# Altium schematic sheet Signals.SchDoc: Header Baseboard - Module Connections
size A4; Organization: Trenz Electronic GmbH; DocumentNumber: TE0304 - Demo Baseboard; Revision: 00; SheetNumber: 2; SheetTotal: 4; Date: 2009-04-16
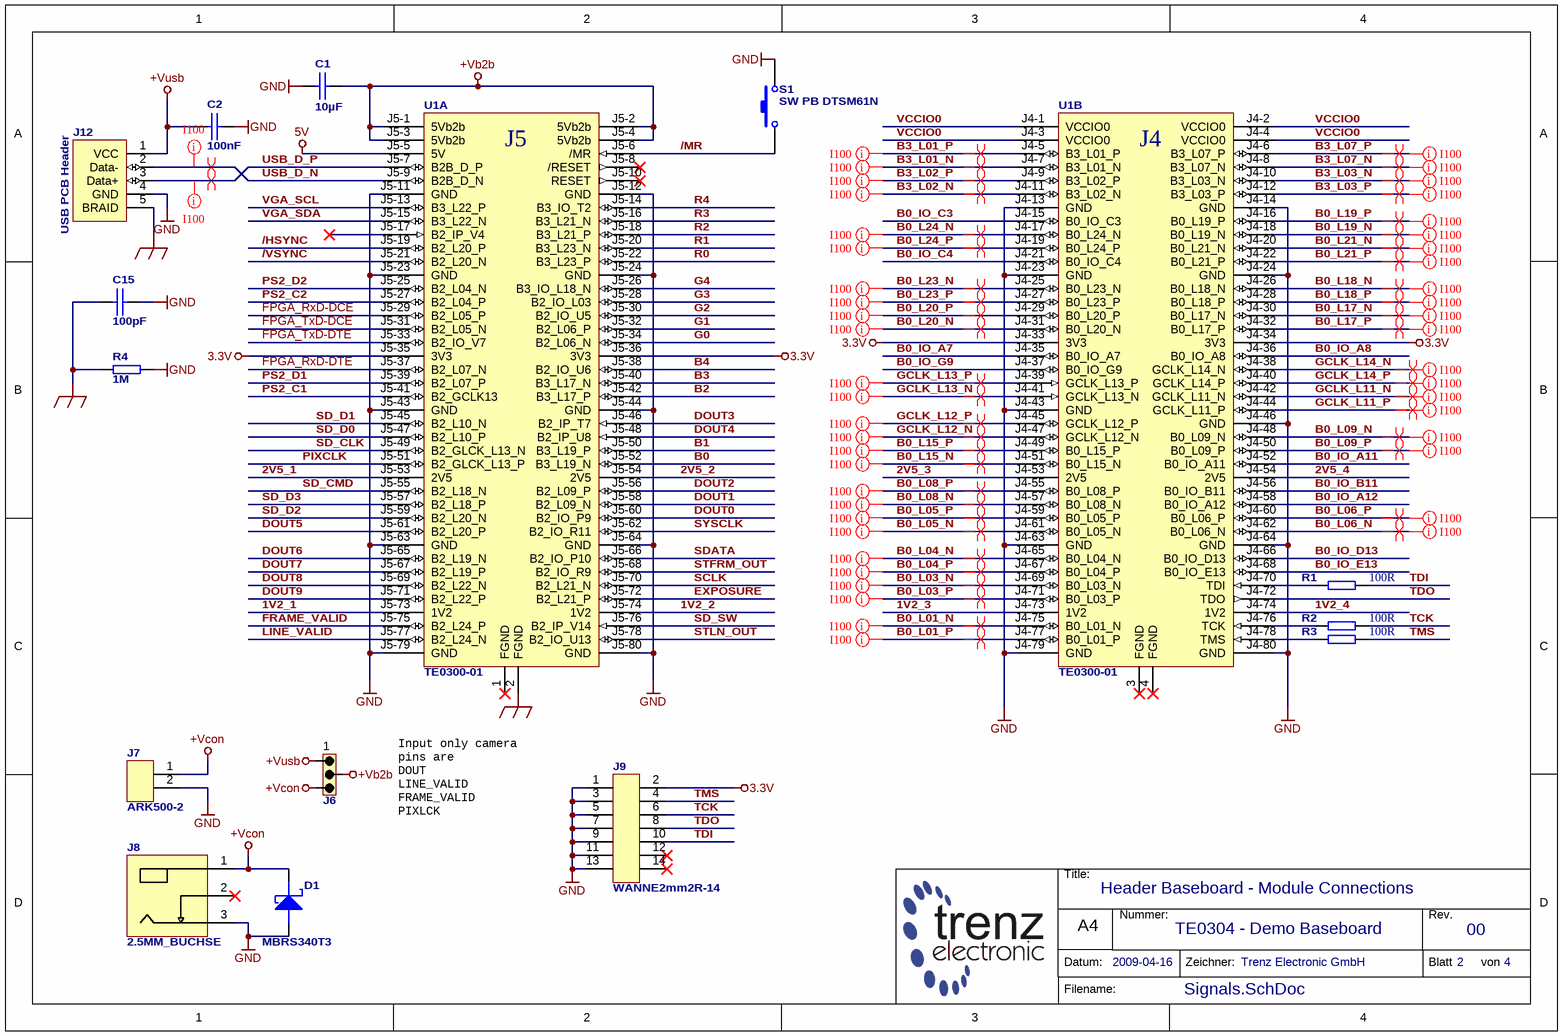
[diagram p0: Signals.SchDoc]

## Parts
C1  10µF  [CAPC2012N]
C2  100nF  [CAPC1608N]
C15  100pF  [CAPC3216N]
D1  MBRS340T3  [MBRS340T3]
J6  JUMPER2.54-3  [JUMPER2_54-3]  (value not drawn)
J7  ARK500-2  [ARK500-2]
J8  2.5MM_BUCHSE  [WS-DC001]
J9  WANNE2mm2R-14  [WANNE2mm2R-14]
J12  USB PCB Header  [14191]
R1  100R  [RESC1609N]
R2  100R  [RESC1609N]
R3  100R  [RESC1609N]
R4  1M  [RESC3216N]
S1  SW PB DTSM61N  [DTSM61N]
U1  TE0300-01  [TE0300-01]  (parts A,B of 2)

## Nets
3.3V: J9.2 U1.J4-33(3V3) U1.J4-34(3V3) U1.J5-35(3V3) U1.J5-36(3V3)
5V: U1.J5-5(5V)
+Vb2b: C1.2 J6.2 U1.J5-1(5Vb2b) U1.J5-2(5Vb2b) U1.J5-3(5Vb2b) U1.J5-4(5Vb2b)
+Vcon: D1.1(CATHODE) J6.3 J7.1 J8.1
+Vusb: C2.1 J6.1 J12.1(VCC)
FGND: C15.1 J12.5(BRAID) R4.1 U1.2(FGND)
GND: C1.1 C2.2 C15.2 D1.2(ANODE) J7.2 J8.3 J9.1 J9.3 J9.5 J9.7 J9.9 J9.11 J9.13 J12.4(GND) R4.2 S1.2 U1.J4-13(GND) U1.J4-14(GND) U1.J4-23(GND) U1.J4-24(GND) U1.J4-43(GND) U1.J4-46(GND) U1.J4-63(GND) U1.J4-64(GND) U1.J4-79(GND) U1.J4-80(GND) U1.J5-11(GND) U1.J5-12(GND) U1.J5-23(GND) U1.J5-24(GND) U1.J5-43(GND) U1.J5-44(GND) U1.J5-63(GND) U1.J5-64(GND) U1.J5-79(GND) U1.J5-80(GND)
1V2_1: U1.J5-73(1V2)
1V2_2: U1.J5-74(1V2)
1V2_3: U1.J4-73(1V2)
1V2_4: U1.J4-74(1V2)
2V5_1: U1.J5-53(2V5)
2V5_2: U1.J5-54(2V5)
2V5_3: U1.J4-53(2V5)
2V5_4: U1.J4-54(2V5)
/HSYNC: U1.J5-19(B2_L20_P)
/MR: S1.1 U1.J5-6(/MR)
/VSYNC: U1.J5-21(B2_L20_N)
B0: U1.J5-52(B3_L19_N)
B0_IO_A7: U1.J4-35(B0_IO_A7)
B0_IO_A8: U1.J4-36(B0_IO_A8)
B0_IO_A11: U1.J4-52(B0_IO_A11)
B0_IO_A12: U1.J4-58(B0_IO_A12)
B0_IO_B11: U1.J4-56(B0_IO_B11)
B0_IO_C3: U1.J4-15(B0_IO_C3)
B0_IO_C4: U1.J4-21(B0_IO_C4)
B0_IO_D13: U1.J4-66(B0_IO_D13)
B0_IO_E13: U1.J4-68(B0_IO_E13)
B0_IO_G9: U1.J4-37(B0_IO_G9)
B0_L01_N: U1.J4-75(B0_L01_N)
B0_L01_P: U1.J4-77(B0_L01_P)
B0_L03_N: U1.J4-69(B0_L03_N)
B0_L03_P: U1.J4-71(B0_L03_P)
B0_L04_N: U1.J4-65(B0_L04_N)
B0_L04_P: U1.J4-67(B0_L04_P)
B0_L05_N: U1.J4-61(B0_L05_N)
B0_L05_P: U1.J4-59(B0_L05_P)
B0_L06_N: U1.J4-62(B0_L06_N)
B0_L06_P: U1.J4-60(B0_L06_P)
B0_L08_N: U1.J4-57(B0_L08_N)
B0_L08_P: U1.J4-55(B0_L08_P)
B0_L09_N: U1.J4-48(B0_L09_N)
B0_L09_P: U1.J4-50(B0_L09_P)
B0_L15_N: U1.J4-51(B0_L15_N)
B0_L15_P: U1.J4-49(B0_L15_P)
B0_L17_N: U1.J4-30(B0_L17_N)
B0_L17_P: U1.J4-32(B0_L17_P)
B0_L18_N: U1.J4-26(B0_L18_N)
B0_L18_P: U1.J4-28(B0_L18_P)
B0_L19_N: U1.J4-18(B0_L19_N)
B0_L19_P: U1.J4-16(B0_L19_P)
B0_L20_N: U1.J4-31(B0_L20_N)
B0_L20_P: U1.J4-29(B0_L20_P)
B0_L21_N: U1.J4-20(B0_L21_N)
B0_L21_P: U1.J4-22(B0_L21_P)
B0_L23_N: U1.J4-25(B0_L23_N)
B0_L23_P: U1.J4-27(B0_L23_P)
B0_L24_N: U1.J4-17(B0_L24_N)
B0_L24_P: U1.J4-19(B0_L24_P)
B1: U1.J5-50(B3_L19_P)
B2: U1.J5-42(B3_L17_P)
B3: U1.J5-40(B3_L17_N)
B3_L01_N: U1.J4-7(B3_L01_N)
B3_L01_P: U1.J4-5(B3_L01_P)
B3_L02_N: U1.J4-11(B3_L02_N)
B3_L02_P: U1.J4-9(B3_L02_P)
B3_L03_N: U1.J4-10(B3_L03_N)
B3_L03_P: U1.J4-12(B3_L03_P)
B3_L07_N: U1.J4-8(B3_L07_N)
B3_L07_P: U1.J4-6(B3_L07_P)
B4: U1.J5-38(B2_IO_U6)
DOUT0: U1.J5-60(B2_IO_P9)
DOUT1: U1.J5-58(B2_L09_N)
DOUT2: U1.J5-56(B2_L09_P)
DOUT3: U1.J5-46(B2_IP_T7)
DOUT4: U1.J5-48(B2_IP_U8)
DOUT5: U1.J5-61(B2_L20_P)
DOUT6: U1.J5-65(B2_L19_N)
DOUT7: U1.J5-67(B2_L19_P)
DOUT8: U1.J5-69(B2_L22_N)
DOUT9: U1.J5-71(B2_L22_P)
EXPOSURE: U1.J5-72(B2_L21_P)
FPGA_RxD-DCE: U1.J5-29(B2_L05_P)
FPGA_RxD-DTE: U1.J5-37(B2_L07_N)
FPGA_TxD-DCE: U1.J5-31(B2_L05_N)
FPGA_TxD-DTE: U1.J5-33(B2_IO_V7)
FRAME_VALID: U1.J5-75(B2_L24_P)
G0: U1.J5-34(B2_L06_N)
G1: U1.J5-32(B2_L06_P)
G2: U1.J5-30(B2_IO_U5)
G3: U1.J5-28(B2_IO_L03)
G4: U1.J5-26(B3_IO_L18_N)
GCLK_L11_N: U1.J4-42(GCLK_L11_N)
GCLK_L11_P: U1.J4-44(GCLK_L11_P)
GCLK_L12_N: U1.J4-47(GCLK_L12_N)
GCLK_L12_P: U1.J4-45(GCLK_L12_P)
GCLK_L13_N: U1.J4-41(GCLK_L13_N)
GCLK_L13_P: U1.J4-39(GCLK_L13_P)
GCLK_L14_N: U1.J4-38(GCLK_L14_N)
GCLK_L14_P: U1.J4-40(GCLK_L14_P)
LINE_VALID: U1.J5-77(B2_L24_N)
PIXCLK: U1.J5-51(B2_GLCK_L13_P)
PS2_C1: U1.J5-41(B2_GCLK13)
PS2_C2: U1.J5-27(B2_L04_P)
PS2_D1: U1.J5-39(B2_L07_P)
PS2_D2: U1.J5-25(B2_L04_N)
R0: U1.J5-22(B3_L23_P)
R1: U1.J5-20(B3_L23_N)
R2: U1.J5-18(B3_L21_P)
R3: U1.J5-16(B3_L21_N)
R4: U1.J5-14(B3_IO_T2)
SCLK: U1.J5-70(B2_L21_N)
SD_CLK: U1.J5-49(B2_GLCK_L13_N)
SD_CMD: U1.J5-55(B2_L18_N)
SD_D0: U1.J5-47(B2_L10_P)
SD_D1: U1.J5-45(B2_L10_N)
SD_D2: U1.J5-59(B2_L20_N)
SD_D3: U1.J5-57(B2_L18_P)
SD_SW: U1.J5-76(B2_IP_V14)
SDATA: U1.J5-66(B2_IO_P10)
STFRM_OUT: U1.J5-68(B2_IO_R9)
STLN_OUT: U1.J5-78(B2_IO_U13)
SYSCLK: U1.J5-62(B2_IO_R11)
TCK: J9.6 R2.2
TDI: J9.10 R1.2
TDO: J9.8 U1.J4-72(TDO)
TMS: J9.4 R3.2
USB_D_N: J12.2(Data-) U1.J5-9(B2B_D_N)
USB_D_P: J12.3(Data+) U1.J5-7(B2B_D_P)
VCCIO0: U1.J4-1(VCCIO0) U1.J4-2(VCCIO0) U1.J4-3(VCCIO0) U1.J4-4(VCCIO0)
VGA_SCL: U1.J5-13(B3_L22_P)
VGA_SDA: U1.J5-15(B3_L22_N)
NetR1_1: R1.1 U1.J4-70(TDI)
NetR2_1: R2.1 U1.J4-76(TCK)
NetR3_1: R3.1 U1.J4-78(TMS)

Not connected (* = marked no-connect by the designer): J8 2*; J9 12* 14*; U1 1(FGND)* 3(FGND)* 4(FGND)* J5-8(/RESET)* J5-10(RESET)* J5-17(B2_IP_V4)*

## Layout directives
net class I100: B0_L01_N, B0_L01_P, B0_L03_N, B0_L03_P, B0_L04_N, B0_L04_P, B0_L05_N, B0_L05_P, B0_L06_N, B0_L06_P, B0_L08_N, B0_L08_P, B0_L09_N, B0_L09_P, B0_L15_N, B0_L15_P, B0_L17_N, B0_L17_P, B0_L18_N, B0_L18_P, B0_L19_N, B0_L19_P, B0_L20_N, B0_L20_P, B0_L21_N, B0_L21_P, B0_L23_N, B0_L23_P, B0_L24_N, B0_L24_P, B3_L01_N, B3_L01_P, B3_L02_N, B3_L02_P, B3_L03_N, B3_L03_P, B3_L07_N, B3_L07_P, GCLK_L11_N, GCLK_L11_P, GCLK_L12_N, GCLK_L12_P, GCLK_L13_N, GCLK_L13_P, GCLK_L14_N, GCLK_L14_P, USB_D_N, USB_D_P
differential pair: B0_L01_N, B0_L01_P, B0_L03_N, B0_L03_P, B0_L04_N, B0_L04_P, B0_L05_N, B0_L05_P, B0_L06_N, B0_L06_P, B0_L08_N, B0_L08_P, B0_L09_N, B0_L09_P, B0_L15_N, B0_L15_P, B0_L17_N, B0_L17_P, B0_L18_N, B0_L18_P, B0_L19_N, B0_L19_P, B0_L20_N, B0_L20_P, B0_L21_N, B0_L21_P, B0_L23_N, B0_L23_P, B0_L24_N, B0_L24_P, B3_L01_N, B3_L01_P, B3_L02_N, B3_L02_P, B3_L03_N, B3_L03_P, B3_L07_N, B3_L07_P, GCLK_L11_N, GCLK_L11_P, GCLK_L12_N, GCLK_L12_P, GCLK_L13_N, GCLK_L13_P, GCLK_L14_N, GCLK_L14_P, USB_D_N, USB_D_P

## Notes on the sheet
- Input only camera pins are
  DOUT
  LINE_VALID
  FRAME_VALID
  PIXLCK

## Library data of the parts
C1 = 22478: AN: 22478; Bezeichnung: KON 10µF 6,3V  X5R SMD; Param 1: 6.3V; Param 2: X5R; Value: 10u
C2 = 21382: AN: 21382; Bezeichnung: KON 100nF 16V X7R SMD; Param 1: 16V; Param 2: X7R; Value: 100n
C15 = 22679: AN: 22679; Bezeichnung: KON 100pF; Value: 100p
D1 = 22887: AN: 22887; Bezeichnung: MBRS340T3 SMD
J6 = 22328: Jumper; AN: 22328; Bezeichnung: Stiftleiste gerade 1-reihig, 3pol.
J7 = 20123: AN: 20123; Bezeichnung: Schraubklemme LP 2 pol ARK500-2
J8 = 22398: 2.5mm Stromversorgungsbuchse; AN: 22398; Bezeichnung: STE 2,5mm Buchse WIESON
J9 = 22744: AN: 22744; Bezeichnung: Stiftleiste Wanne 14polig
J12 = 23194: AN: 23194; Bezeichnung: USB Platinenstecker 5Pol.
R1-R3 = 21380: AN: 21380; Bezeichnung: WID SMD 100R 1% 0,1W; Value: 100
R4 = 22757: AN: 22757; Bezeichnung: WID SMD 1M
S1 = 22596: AN: 22596; Bezeichnung: Taster Miniatur Leiterplatte 1.6N
U1 = TE0300-01: Bezeichnung: Spartan-3E Micromodul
